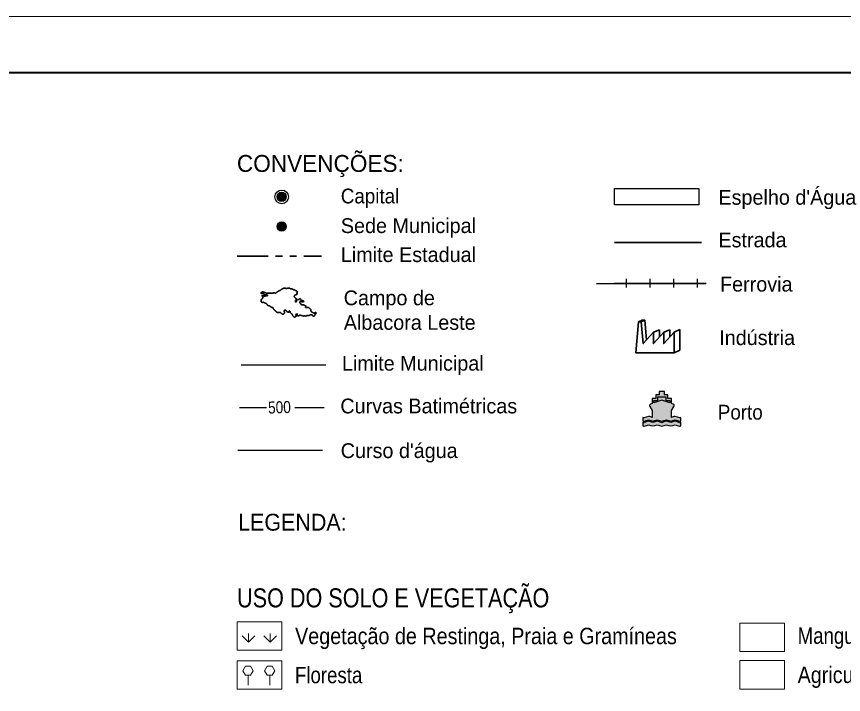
# Model space of a CAD drawing. Extents: x -6.3 to 58.7, y 19.8 to 60.6.
# Drawn here: x 31.28 to 43.55, y 50.52 to 60.58 of the extents above; entities that cross this region are included whole.
import ezdxf

# ---------------------------------------------------------------- set-up
doc = ezdxf.new("R2010")
doc.units = 0
doc.header["$LTSCALE"] = 0.092
doc.linetypes.add('DASH_DOUBLE_DOT', pattern=[9.2, 5, -1.2, 0.3, -1.2, 0.3, -1.2])
for name, color, linetype, lineweight in [('13', 7, 'Continuous', 35), ('58', 7, 'Continuous', 13), ('60', 7, 'Continuous', 40), ('63', 7, 'Continuous', 13)]:
    doc.layers.add(name, color=color, linetype=linetype, lineweight=lineweight)

msp = doc.modelspace()

# ---------------------------------------------------------------- hatches: boundary and pattern name
at = {"layer": '58'}
for points in [[(35.27964, 57.90449, 1), (35.14344, 57.90449, 1)], [(35.2801, 57.46464, 1), (35.14389, 57.46464, 1)], [(41.13521, 54.58199), (41.13521, 54.63187), (41.1252, 54.62767), (41.11686, 54.62619), (41.08704, 54.63654), (41.05206, 54.64682), (41.03097, 54.64375), (40.99949, 54.63104), (40.99949, 54.73387), (41.03309, 54.79539), (41.03687, 54.80426), (41.03826, 54.81165), (41.03509, 54.82051), (41.0213, 54.82837), (40.99949, 54.83753), (40.99949, 54.91466), (40.94131, 54.91466), (40.94131, 54.96613), (40.89281, 54.96613), (40.89281, 55.01767), (40.81527, 55.01767), (40.81527, 54.96613), (40.76682, 54.96613), (40.76682, 54.91466), (40.70864, 54.91466), (40.70864, 54.83676), (40.68684, 54.82837), (40.67377, 54.82128), (40.66987, 54.81324), (40.67104, 54.80456), (40.67499, 54.79539), (40.70864, 54.73387), (40.70864, 54.63104), (40.67699, 54.64375), (40.65608, 54.64682), (40.62137, 54.63654), (40.59122, 54.62619), (40.58244, 54.62767), (40.57292, 54.63187), (40.57292, 54.58199), (40.58366, 54.57632), (40.59439, 54.57472), (40.62332, 54.585), (40.65714, 54.59535), (40.69029, 54.58648), (40.72166, 54.57762), (40.75242, 54.58648), (40.78451, 54.59535), (40.81994, 54.585), (40.85298, 54.57472), (40.88558, 54.585), (40.92357, 54.59535), (40.95677, 54.58648), (40.98642, 54.57762), (41.01674, 54.58648), (41.0505, 54.59535), (41.08493, 54.585), (41.11508, 54.57472), (41.1222, 54.57632)], [(40.9704, 54.84835), (40.85404, 54.89019), (40.73773, 54.84835), (40.73773, 54.88375), (40.79586, 54.88375), (40.79586, 54.93522), (40.91222, 54.93522), (40.91222, 54.88375), (40.9704, 54.88375)], [(41.13521, 54.50942), (41.13521, 54.55977), (41.1252, 54.55557), (41.11719, 54.55409), (41.08793, 54.56444), (41.04916, 54.57472), (41.0169, 54.56556), (40.98781, 54.55652), (40.95828, 54.56556), (40.92162, 54.57472), (40.88619, 54.56444), (40.85437, 54.55409), (40.82178, 54.56444), (40.78651, 54.57472), (40.75164, 54.56556), (40.72027, 54.55652), (40.68968, 54.56556), (40.65513, 54.57472), (40.62226, 54.56444), (40.59228, 54.55409), (40.58305, 54.55557), (40.57292, 54.55977), (40.57292, 54.50942), (40.5826, 54.50427), (40.59306, 54.50268), (40.62426, 54.51296), (40.65714, 54.52324), (40.69029, 54.51444), (40.72166, 54.50557), (40.75242, 54.51444), (40.78451, 54.52324), (40.81994, 54.51296), (40.85298, 54.50268), (40.88691, 54.51296), (40.92357, 54.52324), (40.95555, 54.51444), (40.98642, 54.50557), (41.01779, 54.51444), (41.0505, 54.52324), (41.0837, 54.51296), (41.11508, 54.50268), (41.12537, 54.50427)]]:
    msp.add_hatch(color=256, dxfattribs=at).paths.add_polyline_path(points)

# ---------------------------------------------------------------- linework, layer by layer
at = {"layer": '13'}
for points in [[(35.08258, 56.47716), (35.08117, 56.47689), (35.07502, 56.47654), (35.06887, 56.47672), (35.06272, 56.47716), (35.06211, 56.47716), (35.05605, 56.47716), (35.05578, 56.47716), (35.04972, 56.47707), (35.04357, 56.47698), (35.03742, 56.47698), (35.03127, 56.47716), (35.02697, 56.47733), (35.02082, 56.47751), (35.01475, 56.47716), (35.01071, 56.47672), (35.00465, 56.47593), (34.99859, 56.4754), (34.99674, 56.47549), (34.99059, 56.47619), (34.98471, 56.4776), (34.98321, 56.47804), (34.97741, 56.48006), (34.97162, 56.48217), (34.97153, 56.48217), (34.96573, 56.4841), (34.96002, 56.48612), (34.95413, 56.48796), (34.95404, 56.48796), (34.94825, 56.48972), (34.94245, 56.49192), (34.93797, 56.49385), (34.93559, 56.49411), (34.92944, 56.49385), (34.92821, 56.4935), (34.92233, 56.49192), (34.91802, 56.49078), (34.9124, 56.4884), (34.91029, 56.48673), (34.90616, 56.48217), (34.90344, 56.47672), (34.90563, 56.47224), (34.90932, 56.47224), (34.91196, 56.47224), (34.91222, 56.47224), (34.9182, 56.47312), (34.92294, 56.47329), (34.929, 56.47276), (34.93103, 56.47241), (34.93665, 56.47004), (34.93779, 56.46907), (34.94166, 56.46415), (34.94359, 56.46213), (34.94877, 56.4588), (34.95009, 56.45818), (34.95554, 56.45563)], [(35.37277, 56.534), (35.36697, 56.53637), (35.36126, 56.53822), (35.35722, 56.53883), (35.35107, 56.53927), (35.34501, 56.54041), (35.34387, 56.54085), (35.33824, 56.54358), (35.33622, 56.54481), (35.33086, 56.54788), (35.32533, 56.55025), (35.31935, 56.55148), (35.3132, 56.55166), (35.3089, 56.55131), (35.30284, 56.55025), (35.30231, 56.55017), (35.2966, 56.54841), (35.2908, 56.54621), (35.28772, 56.54525), (35.28184, 56.54402), (35.27701, 56.54481), (35.27103, 56.54665), (35.27086, 56.54674), (35.26488, 56.54815), (35.25882, 56.54894), (35.25425, 56.54938), (35.2481, 56.54938), (35.24757, 56.54929), (35.2416, 56.54815), (35.2358, 56.54621), (35.23018, 56.54358), (35.22631, 56.54164), (35.22104, 56.53857), (35.21577, 56.53549), (35.21515, 56.53506), (35.21006, 56.53172), (35.20496, 56.52829), (35.19987, 56.52486), (35.19468, 56.52161), (35.1924, 56.52021), (35.18713, 56.51722), (35.18168, 56.51432), (35.18098, 56.51406), (35.17553, 56.51133), (35.17, 56.50861), (35.16464, 56.50589), (35.15919, 56.50308), (35.15383, 56.50009), (35.14909, 56.49719), (35.14399, 56.49385), (35.14241, 56.49253), (35.1374, 56.48902), (35.13257, 56.48524), (35.12782, 56.4812), (35.12334, 56.47804), (35.11755, 56.47804), (35.11719, 56.47812), (35.11096, 56.4783), (35.10498, 56.47848), (35.10208, 56.479), (35.09593, 56.47988), (35.09532, 56.47988), (35.08926, 56.47891), (35.08838, 56.47883), (35.08258, 56.47716)], [(35.42021, 56.36795), (35.42461, 56.37226), (35.42496, 56.37533), (35.42496, 56.37806), (35.42487, 56.37929), (35.42461, 56.38526), (35.42452, 56.38587), (35.42461, 56.39202), (35.42469, 56.39484), (35.4232, 56.40055), (35.41784, 56.4023), (35.41424, 56.40353), (35.4102, 56.4081), (35.40703, 56.41153), (35.40203, 56.41531), (35.39807, 56.41935), (35.39807, 56.42207), (35.39807, 56.42295), (35.39878, 56.4291), (35.39983, 56.43507), (35.40159, 56.43947), (35.40528, 56.44439), (35.40721, 56.44606), (35.41292, 56.44843), (35.41494, 56.44896), (35.42083, 56.44983), (35.42689, 56.45115), (35.4326, 56.45344), (35.43532, 56.45475), (35.44024, 56.45844), (35.44288, 56.46328), (35.44288, 56.46635), (35.4406, 56.46907), (35.4362, 56.47312), (35.43805, 56.47848), (35.43972, 56.48217), (35.442, 56.48656), (35.44376, 56.49244), (35.44376, 56.49649), (35.44156, 56.50237), (35.43998, 56.50422), (35.4348, 56.50764), (35.43102, 56.50931), (35.42522, 56.51133), (35.4196, 56.51344), (35.41889, 56.51388), (35.41354, 56.51696), (35.40835, 56.52021), (35.40475, 56.52214), (35.3993, 56.52486), (35.39359, 56.52697), (35.39306, 56.52706), (35.38718, 56.52899), (35.38138, 56.53075), (35.37567, 56.53277), (35.37277, 56.534)], [(34.95554, 56.45563), (34.96134, 56.45344), (34.96257, 56.453), (34.96854, 56.45159), (34.97434, 56.45203), (34.97812, 56.45247), (34.98418, 56.453), (34.98717, 56.45335), (34.99323, 56.453), (34.99771, 56.45071), (35.00219, 56.44667), (35.00228, 56.44658), (35.00263, 56.44043), (34.99999, 56.43683), (34.9963, 56.43771), (34.99094, 56.43859), (34.9869, 56.43947), (34.98418, 56.43903), (34.97979, 56.43727), (34.97926, 56.43701), (34.97355, 56.43507), (34.97109, 56.43437), (34.9652, 56.43305), (34.95905, 56.43235), (34.95387, 56.43244), (34.94781, 56.43367), (34.94763, 56.43384), (34.94192, 56.43622), (34.93621, 56.43824), (34.93384, 56.43841), (34.92769, 56.43859), (34.92751, 56.43868), (34.92136, 56.43903), (34.91732, 56.43455), (34.92013, 56.43182), (34.9218, 56.42963), (34.92215, 56.42928), (34.92769, 56.42655), (34.93173, 56.42515), (34.93392, 56.41979), (34.93349, 56.41487), (34.93269, 56.41311), (34.92988, 56.40766), (34.92953, 56.40643), (34.92813, 56.40055), (34.92725, 56.39853), (34.92321, 56.39378), (34.92031, 56.39167), (34.91512, 56.38842), (34.91486, 56.38825), (34.91064, 56.38394), (34.90906, 56.37981), (34.90836, 56.37366), (34.90818, 56.37243), (34.90695, 56.36646), (34.90563, 56.36057), (34.90511, 56.35688), (34.90476, 56.35082), (34.90476, 56.35082), (34.90616, 56.3481), (34.90836, 56.34493), (34.91064, 56.34397), (34.91152, 56.34353), (34.91644, 56.33993), (34.91679, 56.33984)], [(34.91679, 56.33984), (34.92259, 56.33843), (34.929, 56.33905), (34.93111, 56.33949), (34.93709, 56.34089), (34.94166, 56.34177), (34.94201, 56.34177), (34.94781, 56.33993), (34.94842, 56.33957), (34.95325, 56.33597), (34.95615, 56.33325), (34.9609, 56.32921), (34.96626, 56.32648), (34.97188, 56.32569), (34.97794, 56.32473), (34.97935, 56.3242), (34.98418, 56.32068), (34.98822, 56.31576), (34.99103, 56.31111), (34.99411, 56.30592), (34.99788, 56.30127), (35.00263, 56.29731), (35.00799, 56.29424), (35.00983, 56.29345), (35.01554, 56.29143), (35.02152, 56.28976), (35.02521, 56.28853), (35.03092, 56.28616), (35.03347, 56.28484), (35.03865, 56.28159), (35.04348, 56.27772), (35.04357, 56.27746), (35.04805, 56.27342), (35.05288, 56.26955), (35.05359, 56.26911), (35.05921, 56.26692), (35.06457, 56.26604), (35.06764, 56.26533), (35.07362, 56.26367), (35.07898, 56.26217), (35.08381, 56.25883), (35.08469, 56.25716), (35.08653, 56.25119), (35.08715, 56.24952), (35.08961, 56.24399), (35.09295, 56.23889), (35.09699, 56.23423), (35.10138, 56.22984), (35.10586, 56.22554), (35.11034, 56.22114), (35.11096, 56.22053), (35.115, 56.21587), (35.11904, 56.21121), (35.12299, 56.20656), (35.12703, 56.20199), (35.13143, 56.19786)], [(35.4724, 56.38447), (35.47266, 56.38473), (35.46985, 56.38271), (35.4659, 56.38148), (35.46317, 56.38052), (35.45992, 56.38052), (35.45571, 56.38166), (35.45219, 56.38192), (35.44833, 56.38025), (35.44569, 56.37753), (35.44297, 56.37366), (35.43858, 56.36804), (35.43304, 56.35978), (35.42469, 56.34818), (35.42083, 56.34449), (35.42153, 56.34441), (35.42074, 56.34441), (35.41644, 56.34669), (35.41644, 56.34941), (35.41731, 56.35302), (35.41872, 56.35662), (35.41784, 56.36233), (35.41819, 56.36558), (35.42021, 56.36795)], [(35.57352, 56.28308), (35.57282, 56.2844), (35.56641, 56.2866), (35.56606, 56.28668), (35.56017, 56.28888), (35.55516, 56.29196), (35.55358, 56.29319), (35.54875, 56.2967), (35.54348, 56.30004), (35.5382, 56.30241), (35.53223, 56.30364), (35.52713, 56.30364), (35.52098, 56.3032), (35.51492, 56.30329), (35.50886, 56.30426), (35.50306, 56.30636), (35.50139, 56.30724), (35.49682, 56.31128), (35.49507, 56.31533), (35.49463, 56.31664), (35.49331, 56.32244), (35.49032, 56.32806), (35.48558, 56.33193), (35.4854, 56.33202), (35.47969, 56.33413), (35.47934, 56.33448), (35.47662, 56.33993), (35.47662, 56.34072), (35.47934, 56.34616), (35.48057, 56.34792), (35.48505, 56.35205), (35.48734, 56.35346), (35.49428, 56.35688), (35.50095, 56.35829), (35.50526, 56.35609), (35.50561, 56.35556), (35.50702, 56.34941), (35.50833, 56.34687), (35.51343, 56.34353), (35.51738, 56.34537), (35.52011, 56.3502), (35.5216, 56.35047), (35.52775, 56.34722), (35.53162, 56.3466), (35.53715, 56.34941), (35.53733, 56.3495), (35.53943, 56.35521), (35.53715, 56.35873), (35.53495, 56.3604), (35.52933, 56.36242), (35.52309, 56.36338), (35.51694, 56.3647), (35.5158, 56.36505), (35.51018, 56.36778), (35.50675, 56.36962), (35.50218, 56.37366), (35.50051, 56.37691), (35.49814, 56.38262), (35.49718, 56.38377), (35.49226, 56.38754), (35.48874, 56.3893), (35.48285, 56.39062), (35.47802, 56.38921), (35.47301, 56.38526), (35.4724, 56.38447)], [(35.13143, 56.19786), (35.13274, 56.19663), (35.13775, 56.19312), (35.14311, 56.1903), (35.14786, 56.18846), (35.15383, 56.18749), (35.15401, 56.18749), (35.16007, 56.18793), (35.16595, 56.18978), (35.16798, 56.19083), (35.1736, 56.19285), (35.17659, 56.19285), (35.18256, 56.19118), (35.18643, 56.1896), (35.19196, 56.18679), (35.19697, 56.18354), (35.19829, 56.18249), (35.20285, 56.17818), (35.20725, 56.17405), (35.20971, 56.17194), (35.21454, 56.16834), (35.2199, 56.16509), (35.22341, 56.16333), (35.22939, 56.16201), (35.23299, 56.16254), (35.2387, 56.16509), (35.24011, 56.16588), (35.24538, 56.16931), (35.24942, 56.17361), (35.2517, 56.17897), (35.25214, 56.18231), (35.2517, 56.18837), (35.25144, 56.19364), (35.25082, 56.19962), (35.24968, 56.20533), (35.24854, 56.21121), (35.24854, 56.21244), (35.24942, 56.21842), (35.24977, 56.21912), (35.25425, 56.22334), (35.26031, 56.22571), (35.26172, 56.2258), (35.26778, 56.22571), (35.26963, 56.22527), (35.27507, 56.22246), (35.27701, 56.21982), (35.27947, 56.21403), (35.28228, 56.20858), (35.28535, 56.20594), (35.2908, 56.20269), (35.29528, 56.19918), (35.29756, 56.19786), (35.30328, 56.19558), (35.30389, 56.19549), (35.3096, 56.19329), (35.31101, 56.19312), (35.31733, 56.19329), (35.32129, 56.19522), (35.32199, 56.19637), (35.3226, 56.20269), (35.32304, 56.20682), (35.32445, 56.21183), (35.32805, 56.21306), (35.33157, 56.21078), (35.33385, 56.20629)], [(35.70548, 56.15613), (35.70636, 56.15973), (35.70909, 56.16509), (35.71014, 56.16597), (35.71541, 56.16913), (35.71585, 56.16948), (35.72033, 56.17361), (35.72139, 56.17511), (35.72332, 56.18082), (35.72323, 56.18231), (35.71989, 56.18749), (35.71945, 56.18776), (35.71365, 56.18872), (35.70733, 56.18661), (35.70707, 56.18653), (35.70144, 56.18345), (35.69608, 56.18126), (35.69099, 56.18134), (35.68484, 56.18301), (35.67983, 56.18459), (35.67412, 56.1867), (35.66867, 56.18934), (35.66533, 56.19145), (35.66041, 56.19514), (35.65576, 56.199), (35.6511, 56.20322), (35.64803, 56.20621), (35.64398, 56.21078), (35.64179, 56.21622), (35.6417, 56.21824), (35.64267, 56.22422), (35.64275, 56.22677), (35.64179, 56.23283), (35.64135, 56.23406), (35.6388, 56.23977), (35.63502, 56.24469), (35.63054, 56.24899), (35.63037, 56.24908), (35.6251, 56.25233), (35.61974, 56.25514), (35.61569, 56.25787), (35.61253, 56.26112), (35.60779, 56.26279), (35.60137, 56.26279), (35.59558, 56.26244), (35.58951, 56.26217), (35.58345, 56.26156), (35.57818, 56.26103), (35.57168, 56.26121), (35.56641, 56.26367), (35.56368, 56.26823), (35.5636, 56.26867), (35.56544, 56.27456), (35.56992, 56.27772), (35.57221, 56.27948), (35.57352, 56.28308)], [(35.33385, 56.20629), (35.33499, 56.20146), (35.33657, 56.19558), (35.33886, 56.19083), (35.34237, 56.18574), (35.34439, 56.18301), (35.34843, 56.17853), (35.35318, 56.17449), (35.35573, 56.17291), (35.36109, 56.16975), (35.36574, 56.16606), (35.36574, 56.16606), (35.36864, 56.16087), (35.37049, 56.15499), (35.37251, 56.14892), (35.37514, 56.14356), (35.37848, 56.13847), (35.38235, 56.13372), (35.38463, 56.13118), (35.38902, 56.12705), (35.39008, 56.12626), (35.39535, 56.12301), (35.40124, 56.12116), (35.40176, 56.12116), (35.40791, 56.12116), (35.41248, 56.1223), (35.41819, 56.12476), (35.42135, 56.12661), (35.42267, 56.12801), (35.4254, 56.13372), (35.42566, 56.13408), (35.42715, 56.13996), (35.42707, 56.14216), (35.42364, 56.14761), (35.42083, 56.1498), (35.41784, 56.15437), (35.41916, 56.15613), (35.42223, 56.16017), (35.42338, 56.16087), (35.42953, 56.16237), (35.43032, 56.16263), (35.43585, 56.16456), (35.44209, 56.16606), (35.44235, 56.16606), (35.44833, 56.16465), (35.44833, 56.1636), (35.44376, 56.15841), (35.44033, 56.15437), (35.43884, 56.14892), (35.44209, 56.14409), (35.44218, 56.144), (35.44789, 56.14181), (35.44938, 56.14154), (35.45553, 56.14093), (35.45588, 56.14075), (35.4623, 56.13935)], [(35.4623, 56.13935), (35.46809, 56.13996), (35.47214, 56.14321), (35.47662, 56.14585), (35.47881, 56.14989), (35.47943, 56.15051), (35.48558, 56.15165), (35.48918, 56.14989), (35.49182, 56.14848), (35.4977, 56.14673), (35.49867, 56.14646), (35.50473, 56.14559), (35.51062, 56.14444), (35.51132, 56.14427), (35.51694, 56.14216), (35.52239, 56.13908), (35.52344, 56.13847), (35.52916, 56.13539), (35.53495, 56.1346), (35.53531, 56.13469), (35.54075, 56.13733), (35.54541, 56.13838), (35.55156, 56.13864), (35.55648, 56.13908), (35.55964, 56.13864), (35.55982, 56.13856), (35.56456, 56.1346), (35.56641, 56.13372), (35.57264, 56.13372), (35.57405, 56.13416), (35.57941, 56.13733), (35.58196, 56.13908), (35.58723, 56.14233), (35.59285, 56.14444), (35.59399, 56.14471), (35.60014, 56.14471), (35.60629, 56.14444), (35.61016, 56.14497), (35.61613, 56.14629), (35.61701, 56.14646), (35.6229, 56.14805), (35.6243, 56.14857), (35.62984, 56.15112), (35.63546, 56.1534), (35.63942, 56.15446), (35.64548, 56.15543), (35.65163, 56.15613), (35.65233, 56.15622), (35.65839, 56.15613), (35.65866, 56.15604), (35.66375, 56.15253), (35.66718, 56.14884), (35.67096, 56.14409), (35.67113, 56.14374), (35.67447, 56.13864), (35.67772, 56.13372), (35.67965, 56.13214), (35.68572, 56.131), (35.69029, 56.13372), (35.69178, 56.13487), (35.69661, 56.13864), (35.69977, 56.14269), (35.70285, 56.14805), (35.70373, 56.15024), (35.70548, 56.15613)]]:
    msp.add_lwpolyline(points, dxfattribs=at)
at = {"layer": '58', "lineweight": 35}
for p, q in [((40.14996, 57.2257), (41.44145, 57.2257)), ((40.50639, 56.05163), (40.56005, 56.07381)), ((40.50639, 56.05163), (40.54905, 56.05163)), ((40.54912, 56.05198), (40.50658, 56.05198)), ((40.60209, 56.07399), (40.62793, 55.78305)), ((40.73034, 55.89681), (40.81808, 55.9333)), ((40.81808, 55.9333), (40.81808, 55.8249)), ((40.88283, 55.89681), (40.97066, 55.9333)), ((40.97066, 55.9333), (40.97066, 55.82589)), ((41.03533, 55.89842), (41.12315, 55.93491)), ((41.12315, 55.93491), (41.12315, 55.62823)), ((41.03533, 55.59183), (41.12315, 55.62823))]:
    msp.add_line(p, q, dxfattribs=at)
at = {"layer": '58', "linetype": 'DASH_DOUBLE_DOT', "lineweight": 35}
msp.add_line((34.55102, 57.02619), (35.80454, 57.02619), dxfattribs=at)
at = {"layer": '58', "lineweight": 25}
for p, q in [((39.885, 56.6199), (41.50926, 56.6199)), ((40.1524, 56.62458), (41.51376, 56.62458)), ((40.1524, 56.62458), (41.51376, 56.62458)), ((40.32811, 56.62458), (40.32811, 56.68872)), ((40.32811, 56.56044), (40.32811, 56.62458)), ((40.67954, 56.62458), (40.67954, 56.68872)), ((40.67954, 56.56044), (40.67954, 56.62458)), ((41.03097, 56.62458), (41.03097, 56.68872)), ((41.03097, 56.56044), (41.03097, 56.62458)), ((41.38239, 56.62458), (41.38239, 56.68872)), ((41.38239, 56.56044), (41.38239, 56.62458)), ((34.61098, 55.41282), (35.8645, 55.41282)), ((34.5867, 54.77866), (34.984, 54.77866)), ((35.40528, 54.77866), (35.84022, 54.77866)), ((34.56242, 54.1445), (35.81594, 54.1445))]:
    msp.add_line(p, q, dxfattribs=at)
at = {"layer": '58'}
for p, q in [((34.71821, 51.29702), (34.71821, 51.4286)), ((35.03952, 51.29702), (35.03952, 51.4286)), ((34.71821, 51.29702), (34.62517, 51.39006)), ((34.71821, 51.29702), (34.81125, 51.39006)), ((35.03952, 51.29702), (34.94648, 51.39006)), ((35.03952, 51.29702), (35.13256, 51.39006)), ((34.67489, 50.93919), (34.6373, 50.87408)), ((34.67489, 50.93919), (34.75008, 50.93919)), ((34.78768, 50.87408), (34.75008, 50.93919)), ((34.9962, 50.93919), (34.9586, 50.87408)), ((34.9962, 50.93919), (35.07139, 50.93919)), ((35.10898, 50.87408), (35.07139, 50.93919)), ((34.67489, 50.80896), (34.6373, 50.87408)), ((34.75008, 50.80896), (34.78768, 50.87408)), ((34.9962, 50.80896), (34.9586, 50.87408)), ((35.07139, 50.80896), (35.10898, 50.87408)), ((34.67489, 50.80896), (34.75008, 50.80896)), ((34.71249, 50.65858), (34.71249, 50.80896)), ((34.9962, 50.80896), (35.07139, 50.80896)), ((35.03379, 50.65858), (35.03379, 50.80896))]:
    msp.add_line(p, q, dxfattribs=at)
at = {"layer": '58', "lineweight": 25}
for points in [[(40.14996, 58.02986), (41.40348, 58.02986), (41.40348, 57.78751), (40.14996, 57.78751)], [(41.13521, 54.58199), (41.13521, 54.63187), (41.1252, 54.62767), (41.11686, 54.62619), (41.08704, 54.63654), (41.05206, 54.64682), (41.03097, 54.64375), (40.99949, 54.63104), (40.99949, 54.73387), (41.03309, 54.79539), (41.03687, 54.80426), (41.03826, 54.81165), (41.03509, 54.82051), (41.0213, 54.82837), (40.99949, 54.83753), (40.99949, 54.91466), (40.94131, 54.91466), (40.94131, 54.96613), (40.89281, 54.96613), (40.89281, 55.01767), (40.81527, 55.01767), (40.81527, 54.96613), (40.76682, 54.96613), (40.76682, 54.91466), (40.70864, 54.91466), (40.70864, 54.83676), (40.68684, 54.82837), (40.67377, 54.82128), (40.66987, 54.81324), (40.67104, 54.80456), (40.67499, 54.79539), (40.70864, 54.73387), (40.70864, 54.63104), (40.67699, 54.64375), (40.65608, 54.64682), (40.62137, 54.63654), (40.59122, 54.62619), (40.58244, 54.62767), (40.57292, 54.63187), (40.57292, 54.58199), (40.58366, 54.57632), (40.59439, 54.57472), (40.62332, 54.585), (40.65714, 54.59535), (40.69029, 54.58648), (40.72166, 54.57762), (40.75242, 54.58648), (40.78451, 54.59535), (40.81994, 54.585), (40.85298, 54.57472), (40.88558, 54.585), (40.92357, 54.59535), (40.95677, 54.58648), (40.98642, 54.57762), (41.01674, 54.58648), (41.0505, 54.59535), (41.08493, 54.585), (41.11508, 54.57472), (41.1222, 54.57632)], [(40.9704, 54.84835), (40.85404, 54.89019), (40.73773, 54.84835), (40.73773, 54.88375), (40.79586, 54.88375), (40.79586, 54.93522), (40.91222, 54.93522), (40.91222, 54.88375), (40.9704, 54.88375)], [(41.13521, 54.50942), (41.13521, 54.55977), (41.1252, 54.55557), (41.11719, 54.55409), (41.08793, 54.56444), (41.04916, 54.57472), (41.0169, 54.56556), (40.98781, 54.55652), (40.95828, 54.56556), (40.92162, 54.57472), (40.88619, 54.56444), (40.85437, 54.55409), (40.82178, 54.56444), (40.78651, 54.57472), (40.75164, 54.56556), (40.72027, 54.55652), (40.68968, 54.56556), (40.65513, 54.57472), (40.62226, 54.56444), (40.59228, 54.55409), (40.58305, 54.55557), (40.57292, 54.55977), (40.57292, 54.50942), (40.5826, 54.50427), (40.59306, 54.50268), (40.62426, 54.51296), (40.65714, 54.52324), (40.69029, 54.51444), (40.72166, 54.50557), (40.75242, 54.51444), (40.78451, 54.52324), (40.81994, 54.51296), (40.85298, 54.50268), (40.88691, 54.51296), (40.92357, 54.52324), (40.95555, 54.51444), (40.98642, 54.50557), (41.01779, 54.51444), (41.0505, 54.52324), (41.0837, 54.51296), (41.11508, 54.50268), (41.12537, 54.50427)]]:
    msp.add_lwpolyline(points, close=True, dxfattribs=at)
at = {"layer": '58', "lineweight": 35}
for points in [[(40.50639, 56.0519), (40.46578, 55.59183), (41.03533, 55.59183), (41.03533, 55.89842), (40.88283, 55.72742), (40.88283, 55.89681), (40.73034, 55.72742), (40.73034, 55.89681), (40.57794, 55.72742), (40.54905, 56.0519)], [(40.54905, 56.0519), (40.60209, 56.07399), (40.56005, 56.07381)]]:
    msp.add_lwpolyline(points, dxfattribs=at)
at = {"layer": '58'}
for points in [[(34.5526, 51.60014), (34.5526, 51.17908), (35.21426, 51.17908), (35.21426, 51.60014)], [(42.01216, 51.582), (42.01216, 51.16094), (42.67382, 51.16094), (42.67382, 51.582)], [(34.55088, 51.02034), (34.55088, 50.59929), (35.21254, 50.59929), (35.21254, 51.02034)], [(42.01216, 51.02377), (42.01216, 50.60271), (42.67383, 50.60271), (42.67383, 51.02377)]]:
    msp.add_lwpolyline(points, close=True, dxfattribs=at)
at = {"layer": '58', "lineweight": 25}
for centre, radius in [((35.21154, 57.90474), 0.10128), ((35.21154, 57.90449), 0.0681), ((35.212, 57.46464), 0.0681)]:
    msp.add_circle(centre, radius, dxfattribs=at)
at = {"layer": '60'}
msp.add_lwpolyline([(-3.73781, 29.96257), (-3.73781, 20.65308), (57.84015, 20.65308), (57.84016, 59.74412), (-3.73781, 59.74412), (-3.73781, 40.1986), (-3.73781, 40.1986)], dxfattribs=at)
at = {"layer": '63'}
msp.add_lwpolyline([(-6.28685, 19.8174), (58.67584, 19.8174), (58.67584, 60.5798), (-6.28685, 60.5798)], close=True, dxfattribs=at)

# ---------------------------------------------------------------- texts
at = {"layer": '58'}
for s, height, p in [('CONVENÇÕES:', 0.2507, (34.54683, 58.27525)), ("Espelho d'Água", 0.2194, (41.6939, 57.78819)), ('Sede Municipal', 0.2194, (36.0896, 57.36753)), ('Estrada', 0.2194, (41.6939, 57.15562)), ('Limite Estadual', 0.2194, (36.0896, 56.93777)), ('Ferrovia', 0.2194, (41.71806, 56.49965)), ('Campo de', 0.2194, (36.1322, 56.29636)), ('Albacora Leste', 0.2194, (36.13336, 55.93174)), ('Indústria', 0.2194, (41.70629, 55.70534)), ('Limite Municipal', 0.2194, (36.10613, 55.32615)), ('Curvas Batimétricas', 0.2194, (36.08185, 54.69198)), ("Curso d'água", 0.2194, (36.08764, 54.02942))]:
    msp.add_text(s, height=height, dxfattribs=at).set_placement(p)
for s, height, width, p in [('Capital', 0.2194, 0.95, (36.08914, 57.80713)), ('Porto', 0.2194, 0.95, (41.68545, 54.59982)), ('LEGENDA:', 0.2507, 0.95, (34.56515, 52.95216)), ('USO DO SOLO E VEGETAÇÃO', 0.2822, 0.85, (34.54936, 51.81369)), ('Vegetação de Restinga, Praia e Gramíneas', 0.2434, 0.9, (35.41043, 51.26792)), ('Mangue', 0.2434, 0.85, (42.86999, 51.27199)), ('Floresta', 0.2434, 0.85, (35.40871, 50.68812)), ('Agricultura Cíclica', 0.2434, 0.9, (42.87, 50.69155))]:
    msp.add_text(s, height=height, dxfattribs=dict(at, width=width)).set_placement(p)
at = {"layer": '58', "width": 0.85}
msp.add_text('500', height=0.1785, rotation=1.83, dxfattribs=at).set_placement((35.01183, 54.68819))

doc.saveas('drawing.dxf')
